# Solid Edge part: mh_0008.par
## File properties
Title: work_juice
Author: edge
Template: normal.par
Last saved by: edge
Revision: 22
Application: Solid Edge
Material: steel
非切断部品: False
文書内容のタイプ: 0
Density: 0.00102827763 g/mm^3
Accuracy: 0.99
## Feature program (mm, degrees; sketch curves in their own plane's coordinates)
sketch for "unnamed Protrusion 1" plane through (0, 0, 0) normal (0, 0, 1) x-axis (1, 0, 0)
  circle centre (0, 0) radius 26.5
extrude "unnamed Protrusion 1" add finite 88 along +normal
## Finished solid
Body 1: solid body, 3 faces, 2 edges, 0 vertices.
  Faces by surface: plane 2, cylinder 1
  Edges by curve: circle 2
Bounding box of the edges (mm): 53.000 x 53.000 x 88.000, from (-26.5, -26.5, 0) to (26.5, 26.5, 88).
Cylindrical faces by radius (mm): R26.5 x1
Planar faces by outward normal: +z 1, -z 1
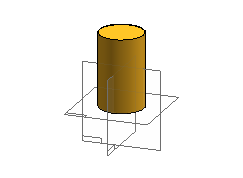
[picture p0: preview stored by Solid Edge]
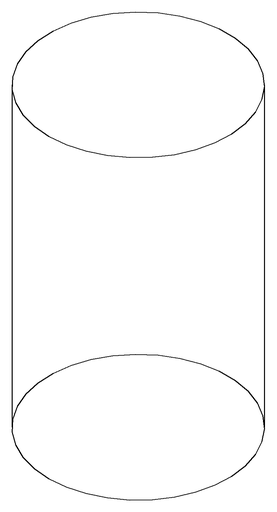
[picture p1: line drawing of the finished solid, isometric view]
